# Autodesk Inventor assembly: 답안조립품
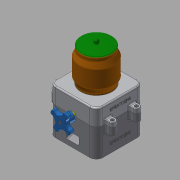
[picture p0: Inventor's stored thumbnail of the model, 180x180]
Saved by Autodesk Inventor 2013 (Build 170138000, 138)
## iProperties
Created: 2018-01
Part Number: 답안조립품
Document SubType Name: Assembly
Designer: Administrator
Author: Administrator
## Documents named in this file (9)
- C:\Users\Administrator\Desktop\480108V1005\답안조립품.iam
- C:\Users\Administrator\Desktop\480108V1005\본체.ipt
- C:\Users\Administrator\Desktop\480108V1005\본체커버.ipt
- C:\Users\Administrator\Desktop\480108V1005\볼트 M3x12.ipt
- C:\Users\Administrator\Desktop\480108V1005\볼트 M4x12.ipt
- C:\Users\Administrator\Desktop\480108V1005\용기.ipt
- C:\Users\Administrator\Desktop\480108V1005\용기캡.ipt
- C:\Users\Administrator\Desktop\480108V1005\핸들.ipt
- C:\Users\Administrator\Desktop\480108V1005\핸들축.ipt
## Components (2 placed, 2 different names)
1. 핸들:1
2. 핸들축:1
## Component patterns: 구성요소 패턴 1:2 (2 elements)
